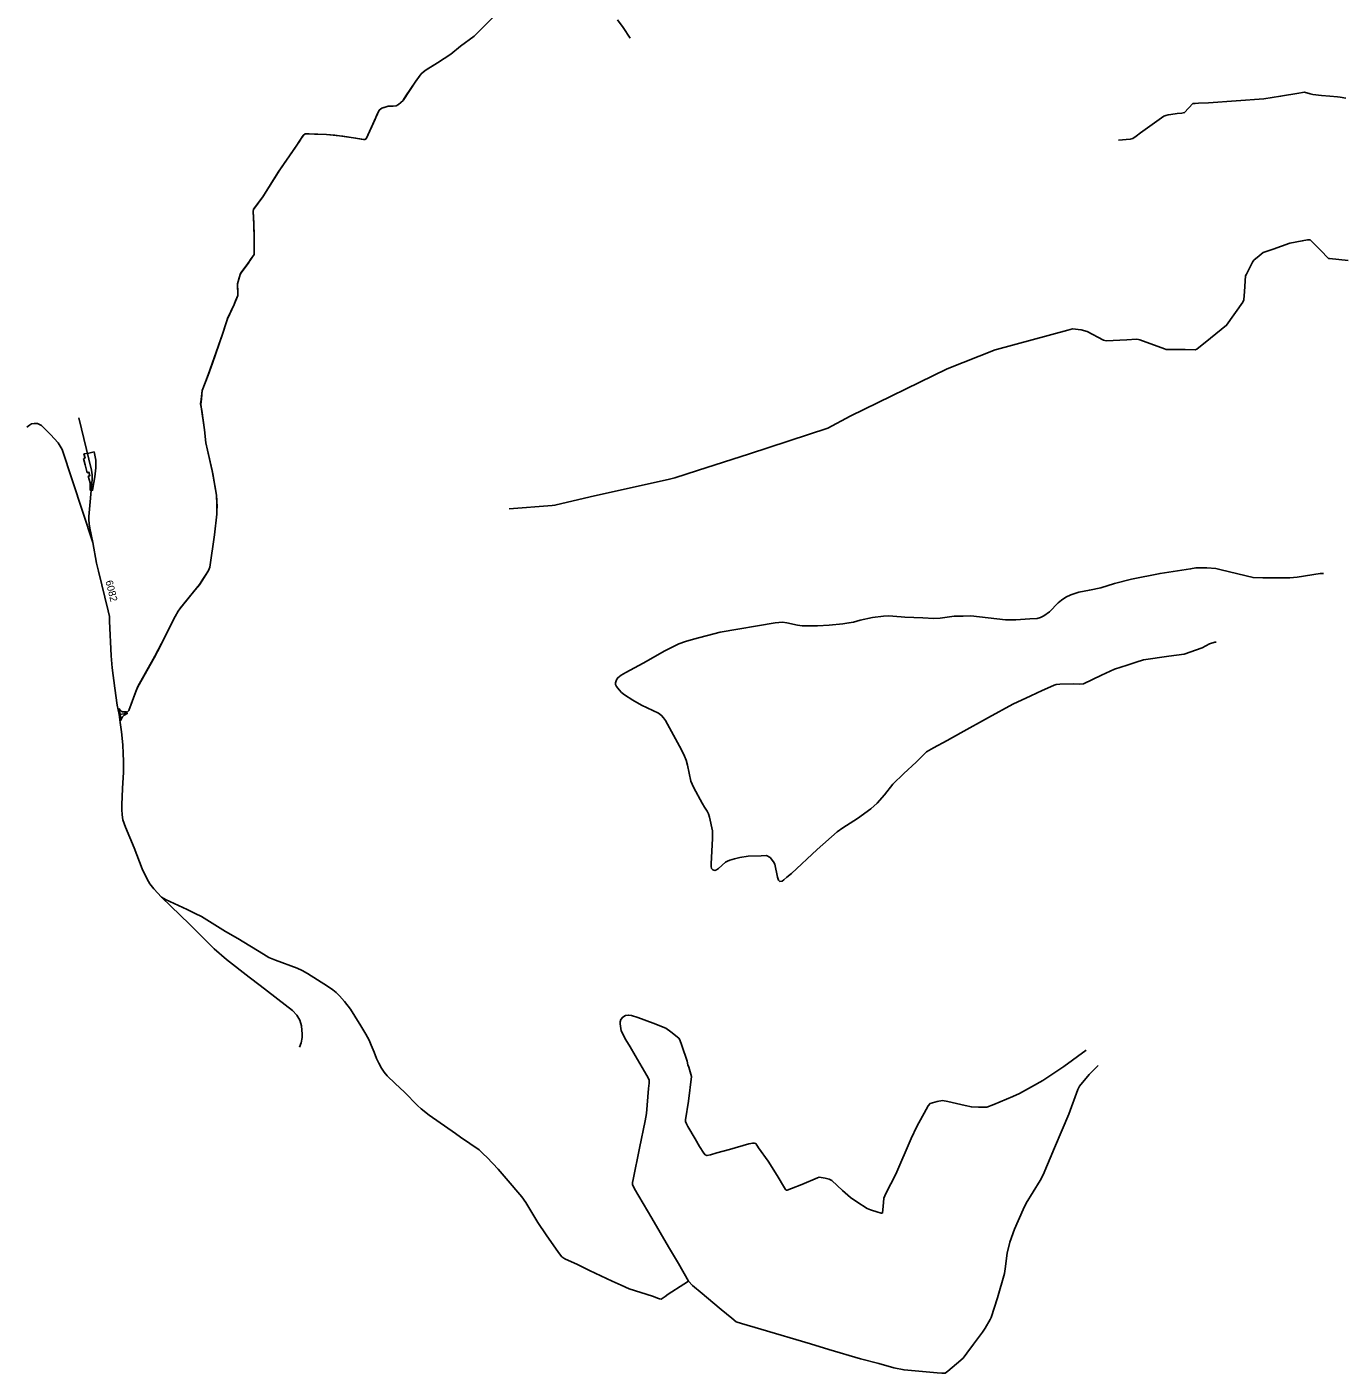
# Model space of a CAD drawing. Extents: x -444937 to -440733, y -1145714 to -1129798.
# Drawn here: x -444937 to -443130, y -1134559 to -1132712 of the extents above; entities that cross this region are included whole.
import ezdxf

# ---------------------------------------------------------------- set-up
doc = ezdxf.new("R2010")
doc.units = 0
for name, color, linetype in [('Vrstva 12', 7, 'Continuous'), ('Vrstva 29', 7, 'Continuous'), ('Vrstva 75', 7, 'Continuous'), ('Vrstva 8', 7, 'Continuous')]:
    doc.layers.add(name, color=color, linetype=linetype)

msp = doc.modelspace()

# ---------------------------------------------------------------- linework, layer by layer
at = {"layer": 'Vrstva 12'}
for points in [[(-444810.7, -1133655.8), (-444804, -1133654.8), (-444800.5, -1133653.5), (-444797.4, -1133650.5), (-444788, -1133624.4), (-444785.2, -1133617.7), (-444762.9, -1133578.2), (-444754.2, -1133561.6), (-444744.3, -1133542.3), (-444733.8, -1133521.3), (-444729.9, -1133513.9), (-444725.7, -1133508.6), (-444706.5, -1133485), (-444700.6, -1133477.9), (-444694.1, -1133467.9), (-444689.6, -1133460.8), (-444688.1, -1133458.5), (-444686.5, -1133453.9), (-444679.9, -1133409.3), (-444676.7, -1133381.1), (-444676.5, -1133375.2), (-444676.2, -1133370.9), (-444677.2, -1133354.9), (-444683.2, -1133321.2), (-444689.7, -1133293.2), (-444691.9, -1133283), (-444693.6, -1133265.4), (-444697.8, -1133236.9), (-444698.8, -1133230.7), (-444697.9, -1133223), (-444697.5, -1133216.2), (-444696.9, -1133211.3), (-444693.8, -1133203.1), (-444688.5, -1133189.8), (-444682.9, -1133174.4), (-444668.8, -1133134.2), (-444664.8, -1133121.3), (-444662.2, -1133112.9), (-444652.8, -1133093.2), (-444648, -1133081.2), (-444648, -1133075.9), (-444648.2, -1133065.2), (-444644.5, -1133052.1), (-444643.3, -1133049.9), (-444633.9, -1133036.9), (-444630.5, -1133031.8), (-444625.5, -1133024.8), (-444625.5, -1132998.6), (-444626, -1132982.6), (-444626.4, -1132973.1), (-444626.8, -1132966.9), (-444626.8, -1132965.1), (-444626.4, -1132963), (-444613.4, -1132945.4), (-444590.2, -1132908.7), (-444567.2, -1132874.9), (-444563.8, -1132870), (-444559.6, -1132863.3), (-444557.8, -1132861), (-444556, -1132859.6), (-444550.6, -1132859.3), (-444542.8, -1132859.6), (-444526.3, -1132859.9), (-444515, -1132861.1), (-444486, -1132865.2), (-444478.6, -1132866.3), (-444475.4, -1132867), (-444473.5, -1132866.9), (-444472, -1132866.1), (-444454, -1132826.8), (-444450.4, -1132824.1), (-444445.7, -1132822.4), (-444441.8, -1132821.1), (-444435, -1132821.1), (-444430.8, -1132820.8), (-444427.7, -1132819.1), (-444421.2, -1132813.3), (-444403.6, -1132786.9), (-444396.3, -1132776.9), (-444390.9, -1132772.4), (-444374, -1132761.8), (-444355.9, -1132749.9), (-444342.4, -1132738.9), (-444323.9, -1132725.4), (-444287.2, -1132688.4)], [(-444127.1, -1132702.6), (-444119.5, -1132713.5), (-444109.5, -1132728.1)], [(-443439.9, -1132867.8), (-443423.7, -1132866.7), (-443420.1, -1132865.6), (-443415.5, -1132862.2), (-443409.8, -1132858), (-443380.8, -1132837.3), (-443377.7, -1132835.1), (-443374.7, -1132833.9), (-443371.9, -1132833.2), (-443368.2, -1132832.8), (-443359.4, -1132831.3), (-443353.1, -1132830.6), (-443349.3, -1132830.1), (-443338, -1132817.7), (-443334.6, -1132817.5), (-443330, -1132817.3), (-443316.2, -1132816.5), (-443240.3, -1132811), (-443217.5, -1132807.6), (-443192.3, -1132803.2), (-443187.4, -1132802.3), (-443184.6, -1132802.1), (-443177, -1132804.2), (-443173.1, -1132805.2), (-443161.5, -1132806.4), (-443150.1, -1132807.4), (-443139.3, -1132808.4), (-443135.8, -1132808.8), (-443127.9, -1132810.4)], [(-443125, -1133032.9), (-443150.3, -1133030.4), (-443151.9, -1133030.2), (-443153.4, -1133028.6), (-443161.1, -1133020.7), (-443171.9, -1133009.7), (-443177.1, -1133004.4), (-443180.5, -1133004.5), (-443187.7, -1133006.1), (-443204.6, -1133009.4), (-443227.8, -1133017.3), (-443241.4, -1133021.8), (-443246.8, -1133026.4), (-443254.2, -1133032.7), (-443255.9, -1133035.1), (-443264.4, -1133051.8), (-443265.5, -1133053.8), (-443267.2, -1133075.6), (-443268, -1133086.8), (-443269.3, -1133090.1), (-443291.6, -1133121.7), (-443313.7, -1133139.6), (-443332.4, -1133154.8), (-443334.7, -1133155.7), (-443348.2, -1133155.3), (-443372.1, -1133154.9), (-443374.3, -1133154.9), (-443376.7, -1133154.3), (-443410.4, -1133141.9), (-443412.6, -1133141.4), (-443415.2, -1133141.1), (-443428.6, -1133141.8), (-443456.6, -1133143.3), (-443460.3, -1133142.2), (-443482.8, -1133130.4), (-443491, -1133127.9), (-443502.9, -1133126.9), (-443509.5, -1133128.6), (-443607.2, -1133155.1), (-443609.1, -1133155.6), (-443674.9, -1133181.8), (-443807.9, -1133246.7), (-443838.6, -1133262.8), (-443946.2, -1133298.1), (-444017.4, -1133320.9), (-444048.5, -1133331.1), (-444055.6, -1133332.9), (-444164.4, -1133357.4), (-444213, -1133368.8), (-444216.8, -1133369.2), (-444275.6, -1133373.9)], [(-444846.6, -1133419.8), (-444888.9, -1133292.1), (-444894.2, -1133283), (-444904.8, -1133271.9), (-444917.3, -1133259.2), (-444922.8, -1133256.5), (-444926.9, -1133256.5), (-444931, -1133257.2), (-444933.6, -1133258.7), (-444937.2, -1133261.6)], [(-444029.7, -1134433.4), (-444036.1, -1134437.5), (-444057.5, -1134451.4), (-444061.9, -1134454.6), (-444067.2, -1134458.1), (-444069.4, -1134457.7), (-444070.7, -1134457.1), (-444079.3, -1134454.1), (-444111.2, -1134443.9), (-444122.2, -1134438.9), (-444134.5, -1134433.4), (-444165.4, -1134418.5), (-444181.8, -1134410.6), (-444199.3, -1134402.5), (-444203.3, -1134400.1), (-444208.1, -1134393.8), (-444224.9, -1134369.7), (-444236.5, -1134352.7), (-444252.8, -1134325.6), (-444258.3, -1134317.7), (-444279.7, -1134292.7), (-444290.6, -1134279.9), (-444306, -1134263.8), (-444311.2, -1134258.5), (-444316.9, -1134253.2), (-444342.3, -1134235.7), (-444349.4, -1134230.9), (-444385.3, -1134205.4), (-444396.4, -1134196.8), (-444401.3, -1134192.1), (-444419.3, -1134173.8), (-444432.2, -1134162.1), (-444443.1, -1134151.6), (-444447.4, -1134146.5), (-444450.9, -1134140.9), (-444454.5, -1134134.2), (-444457.5, -1134127.9), (-444461.1, -1134119.1), (-444464.8, -1134109.5), (-444467.8, -1134102.9), (-444472.3, -1134094.3), (-444479, -1134082.8), (-444487.5, -1134069.6), (-444493.5, -1134060.2), (-444501.4, -1134049.5), (-444508.3, -1134041.9), (-444512.9, -1134037.4), (-444517.8, -1134033.5), (-444524.9, -1134028.5), (-444552.5, -1134011.3), (-444559.6, -1134007.3), (-444566.4, -1134004), (-444596.2, -1133993.1), (-444605.2, -1133989.1), (-444612.7, -1133984.7), (-444647.7, -1133963.4), (-444664.8, -1133953.5), (-444697.7, -1133932.8), (-444706.4, -1133928.7), (-444717.5, -1133923.6), (-444747.3, -1133909.8), (-444752.5, -1133906.4), (-444763, -1133895.2), (-444768.5, -1133888), (-444772.2, -1133882), (-444779.1, -1133867.6), (-444790.3, -1133838.9), (-444802.2, -1133810.5), (-444805.5, -1133800.4), (-444806.7, -1133793.6), (-444807.1, -1133786.4), (-444807.1, -1133780), (-444806.1, -1133757.2), (-444804.8, -1133734.8), (-444804.8, -1133720), (-444805.1, -1133709.2), (-444805.6, -1133697.4), (-444807.3, -1133679.6), (-444809.1, -1133666.7), (-444810.7, -1133655.8), (-444813.3, -1133643), (-444816.6, -1133619.9), (-444820.5, -1133591.7), (-444821.8, -1133575.2), (-444823.9, -1133527.7), (-444824, -1133521.2), (-444825.6, -1133513.8), (-444839.1, -1133459.1), (-444841.7, -1133448.2), (-444846.6, -1133419.8), (-444851.1, -1133400.2), (-444851.9, -1133394.3), (-444852.4, -1133388.4), (-444852.2, -1133384.1), (-444847.6, -1133333.3), (-444847.7, -1133327.2), (-444848.7, -1133320.5), (-444865.8, -1133249)], [(-443836.6, -1133533.2), (-443852.8, -1133534.1), (-443865.6, -1133534.4), (-443873.8, -1133534), (-443880.1, -1133533.4), (-443894.7, -1133530.3), (-443900.7, -1133529.4), (-443906, -1133529.7), (-443910.9, -1133530.2), (-443986.1, -1133542.8), (-444023, -1133552.5), (-444033.6, -1133555.6), (-444043.1, -1133559.1), (-444062.1, -1133568.4), (-444091.9, -1133585.3), (-444115.8, -1133598.1), (-444122.2, -1133601.8), (-444126.7, -1133605.4), (-444128.5, -1133608.4), (-444129.8, -1133612.3), (-444129.7, -1133614.7), (-444128.6, -1133617.3), (-444125, -1133622.1), (-444121.5, -1133625.8), (-444117.7, -1133628.7), (-444106.1, -1133636.3), (-444094.4, -1133642.9), (-444070.8, -1133654.2), (-444066.7, -1133657.1), (-444063.8, -1133660.4), (-444061.3, -1133664.1), (-444039.2, -1133704.5), (-444035.2, -1133713.2), (-444033, -1133718.7), (-444031.1, -1133725.3), (-444026.3, -1133747.2), (-444024.7, -1133751.6), (-444022.2, -1133756.3), (-444010.9, -1133777.6), (-444007.6, -1133782.8), (-444004.1, -1133788.4), (-444002.5, -1133792.3), (-444000.9, -1133796.8), (-443997, -1133815.4), (-443996.7, -1133820.5), (-443996.9, -1133826.1), (-443998.8, -1133860.7), (-443998.7, -1133864.5), (-443998.1, -1133867.1), (-443996.3, -1133869), (-443993.5, -1133869.7), (-443991.1, -1133869), (-443988.7, -1133867.1), (-443978.8, -1133858.3), (-443976.2, -1133857.1), (-443973, -1133855.6), (-443966.4, -1133854)], [(-444752.5, -1133906.4), (-444714.3, -1133943.6), (-444690.6, -1133967.1), (-444680.3, -1133977.2), (-444663.5, -1133991.8), (-444632.4, -1134016.4), (-444617.4, -1134027.5), (-444572.8, -1134062), (-444567, -1134068.4), (-444562.9, -1134075.2), (-444560.5, -1134083), (-444559.5, -1134094.5), (-444559.8, -1134098.9), (-444561.2, -1134106.4), (-444563.2, -1134112.5)], [(-443484.1, -1134116.4), (-443514.7, -1134139), (-443543.5, -1134158.2), (-443559.3, -1134166.8), (-443575.7, -1134176), (-443584.9, -1134179.9), (-443610.7, -1134190.8), (-443620.5, -1134194.8), (-443625.4, -1134194.8), (-443631.8, -1134194.7), (-443641.6, -1134194.3), (-443650.1, -1134192.4), (-443673.9, -1134186.9), (-443681.3, -1134185.5), (-443688.6, -1134187), (-443698.2, -1134189.6), (-443700.8, -1134193), (-443703.6, -1134197.9), (-443716.7, -1134221.2), (-443724.1, -1134237.5), (-443745.2, -1134286.4), (-443758.8, -1134313), (-443761.6, -1134319.6), (-443762.5, -1134331.1), (-443763.4, -1134339.6), (-443764.2, -1134340.2), (-443765.2, -1134340), (-443767, -1134339.5), (-443769.9, -1134338.8), (-443780.2, -1134335.3), (-443784.7, -1134333.7), (-443798.9, -1134324.4), (-443807.6, -1134318.7), (-443818.6, -1134308.9), (-443833.3, -1134295.2), (-443836.8, -1134293.6), (-443842.3, -1134292.1), (-443850.5, -1134290.6), (-443852.9, -1134291.6), (-443874.3, -1134300.5), (-443888.5, -1134306.4), (-443894.5, -1134308.7), (-443895.8, -1134308.5), (-443896.7, -1134307.7), (-443898.2, -1134305.2), (-443908.3, -1134288.4), (-443920.4, -1134268.7), (-443933.6, -1134250.4), (-443937.5, -1134244.5), (-443939.2, -1134243.8), (-443941.5, -1134243.8), (-443947, -1134245.1), (-443973.5, -1134252.5), (-443990.8, -1134257.4), (-443999.4, -1134260.1), (-444004.4, -1134261.1), (-444006.8, -1134260), (-444008.8, -1134257.8), (-444014.4, -1134248.4), (-444020.6, -1134238.2), (-444030.5, -1134221), (-444032.6, -1134217.5), (-444034, -1134214.4), (-444033.9, -1134212), (-444029.5, -1134186.5), (-444025.4, -1134152.4), (-444029.4, -1134139.8), (-444030.5, -1134136.4), (-444031.7, -1134131.3), (-444038.7, -1134109.9), (-444041.4, -1134102.2), (-444042.9, -1134100.1), (-444054.1, -1134091.3), (-444060.9, -1134086.3), (-444078.2, -1134079.3), (-444099.3, -1134071.7), (-444107.9, -1134068.9), (-444112.2, -1134068.2), (-444116, -1134069), (-444119.9, -1134071.1), (-444122.6, -1134074.3), (-444123.3, -1134077.4), (-444123.6, -1134080.2), (-444122.3, -1134089.9), (-444115.6, -1134102.4), (-444109.9, -1134112), (-444103, -1134123.5), (-444086.9, -1134151.2), (-444083.6, -1134157.3), (-444083.7, -1134161.7), (-444084.5, -1134168.8), (-444087.3, -1134203.1), (-444089, -1134213.2), (-444096.9, -1134250.7), (-444105.5, -1134293.7), (-444106.7, -1134298), (-444106.6, -1134300.6), (-444103.8, -1134306.6), (-444079.9, -1134346.7), (-444057.3, -1134386.2), (-444043.6, -1134409.3), (-444029.7, -1134433.4), (-444024.2, -1134439.2), (-444010.8, -1134450.3), (-443996.1, -1134462.6), (-443984.9, -1134472), (-443970.2, -1134484.1), (-443964.2, -1134489.1), (-443957.2, -1134491.3)], [(-443957.2, -1134491.3), (-443930.4, -1134499.2), (-443862.4, -1134519.2), (-443837.3, -1134527), (-443793.8, -1134539.9), (-443768.7, -1134546.1), (-443748, -1134552.3), (-443733.9, -1134555.2), (-443688.5, -1134559.2), (-443682.3, -1134559.4), (-443677.6, -1134559.4), (-443673.9, -1134556.8), (-443662.1, -1134546.8), (-443653.1, -1134538.9), (-443648.1, -1134531.9), (-443638.9, -1134519.8), (-443626.6, -1134503.3), (-443622.9, -1134497.7), (-443615.9, -1134486), (-443614.4, -1134483), (-443605.7, -1134456.1), (-443596.4, -1134422.7), (-443595.2, -1134416.4), (-443592.5, -1134394.8), (-443588.9, -1134380), (-443582.3, -1134361.9), (-443570.7, -1134335), (-443566.3, -1134326.5), (-443547.4, -1134295.2), (-443543.4, -1134287.6), (-443527.8, -1134250.5), (-443517.1, -1134225.7), (-443508.2, -1134204.4), (-443495.7, -1134170.2), (-443493.2, -1134165.6), (-443479.9, -1134149.8), (-443467.6, -1134137.6)]]:
    msp.add_lwpolyline(points, dxfattribs=at)
msp.add_lwpolyline([(-444811, -1133647.8), (-444809.5, -1133650.1), (-444808.1, -1133651.4), (-444806, -1133652.2), (-444804.1, -1133652.3), (-444801, -1133652), (-444799.6, -1133654.6), (-444803.9, -1133656.8), (-444806.2, -1133659), (-444807.2, -1133660.7), (-444808.2, -1133663.7), (-444809.5, -1133655.4)], close=True, dxfattribs=at)
at = {"layer": 'Vrstva 29'}
msp.add_lwpolyline([(-444859.5, -1133304.6), (-444857.2, -1133313.2), (-444854.4, -1133324.1), (-444852.2, -1133323.5), (-444850.8, -1133328.2), (-444853, -1133328.8), (-444851.8, -1133333.5), (-444850.7, -1133337.8), (-444850.5, -1133339.9), (-444850.7, -1133348), (-444847.2, -1133348.3), (-444844.1, -1133329.9), (-444842.7, -1133317.6), (-444842.7, -1133311.8), (-444842.7, -1133306.7), (-444845.1, -1133295.5), (-444852.5, -1133297.1), (-444859, -1133298.4), (-444857.5, -1133304.1)], close=True, dxfattribs=at)
at = {"layer": 'Vrstva 75'}
for points in [[(-444810.7, -1133655.8), (-444804, -1133654.8), (-444800.5, -1133653.5), (-444797.4, -1133650.5), (-444788.5, -1133625.9), (-444786, -1133619.8), (-444785, -1133617.6), (-444763.9, -1133579.9), (-444761.6, -1133575.9), (-444752.5, -1133558.3), (-444733.8, -1133521.3), (-444729.9, -1133513.9), (-444726.6, -1133509.7), (-444708.6, -1133487.7), (-444700.6, -1133477.5), (-444694.8, -1133468.9), (-444691.4, -1133463.5), (-444688.3, -1133458.5), (-444686.5, -1133453.9), (-444679.9, -1133409.3), (-444676.7, -1133381.1), (-444676.5, -1133375.2), (-444676.8, -1133367.2), (-444677.2, -1133354.9), (-444682.3, -1133325.5), (-444689.7, -1133293.2), (-444691.9, -1133283), (-444693.6, -1133265.4), (-444697.5, -1133238.8), (-444699.1, -1133229.4), (-444698.1, -1133223.9), (-444697.1, -1133215.4), (-444696.9, -1133211.3), (-444688.7, -1133190.2), (-444682.7, -1133174), (-444668.8, -1133134.2), (-444663.2, -1133115.9), (-444662.2, -1133112.7), (-444652.8, -1133093.2), (-444651.2, -1133088.2), (-444649.3, -1133084.2), (-444648, -1133081.2), (-444648.2, -1133065.2), (-444645.9, -1133056.8), (-444644.5, -1133052.1), (-444643.6, -1133050.1), (-444634.4, -1133037.3), (-444630.5, -1133031.9), (-444627.8, -1133027.9), (-444625.5, -1133024.8), (-444625.5, -1133001.4), (-444626, -1132985.2), (-444626.4, -1132973.1), (-444626.9, -1132965.7), (-444626.4, -1132962.7), (-444613.4, -1132945.4), (-444592.4, -1132911.9), (-444569, -1132877.6), (-444561.9, -1132866.9), (-444557.9, -1132860.8), (-444555.7, -1132859.4), (-444550.1, -1132859.3), (-444526.3, -1132859.9), (-444503.9, -1132862.6), (-444477.9, -1132866.3), (-444475, -1132867), (-444473.5, -1132866.9), (-444472.8, -1132866.6), (-444471.5, -1132865.1), (-444459.6, -1132839), (-444457.5, -1132834.4), (-444456.7, -1132832.4), (-444455.7, -1132830.2), (-444454, -1132826.8), (-444450.4, -1132824.1), (-444441.8, -1132821.1), (-444430.8, -1132820.7), (-444427.6, -1132818.9), (-444421.2, -1132812.9), (-444417.3, -1132807.1), (-444404.6, -1132788.2), (-444396.3, -1132776.9), (-444389.5, -1132771.3), (-444374, -1132761.8), (-444355.9, -1132749.9), (-444342.4, -1132738.9), (-444323.9, -1132725.4), (-444286.2, -1132687.7)], [(-444846.6, -1133419.8), (-444888.9, -1133292.1), (-444894.2, -1133283), (-444904.8, -1133271.9), (-444917.3, -1133259.2), (-444922.8, -1133256.5), (-444926.9, -1133256.5), (-444931, -1133257.2), (-444933.6, -1133258.7), (-444937.2, -1133261.6)], [(-444810.7, -1133655.8), (-444813.3, -1133643), (-444816.6, -1133619.9), (-444820.5, -1133591.7), (-444821.8, -1133575.2), (-444823.9, -1133527.7), (-444824, -1133521.2), (-444825.6, -1133513.8), (-444839.1, -1133459.1), (-444841.7, -1133448.2), (-444846.6, -1133419.8)]]:
    msp.add_lwpolyline(points, dxfattribs=at)
at = {"layer": 'Vrstva 8'}
for points in [[(-443158.7, -1133462.4), (-443163, -1133462.4), (-443194.6, -1133467.5), (-443204.6, -1133468.4), (-443226.3, -1133468.5), (-443241.7, -1133468.4), (-443255.2, -1133468), (-443299.1, -1133457.3), (-443306.5, -1133455.6), (-443318.9, -1133454.6), (-443333.9, -1133454.8), (-443340.9, -1133456.1), (-443382.8, -1133462.2), (-443421.9, -1133470.3), (-443445.5, -1133476.3), (-443463.9, -1133482.2), (-443479.7, -1133485.2), (-443494.3, -1133488), (-443505.2, -1133491.7), (-443512, -1133495.1), (-443517.9, -1133498.8), (-443522.8, -1133502.5), (-443534.7, -1133515.1), (-443542.3, -1133520.7), (-443546.8, -1133522.9), (-443551.5, -1133524), (-443561.5, -1133524.5), (-443580.6, -1133525.8), (-443589, -1133526.2), (-443594.7, -1133525.8), (-443642.6, -1133520.7), (-443653, -1133520.9), (-443665.4, -1133520.9), (-443684.5, -1133523.7), (-443693.2, -1133524.3), (-443708.2, -1133523.3), (-443732.9, -1133522.3), (-443738.1, -1133521.9), (-443755.2, -1133520.4), (-443762.1, -1133520.8), (-443777.2, -1133522.6), (-443794.2, -1133526.3), (-443803.5, -1133529), (-443809.7, -1133530.3), (-443818, -1133531.6), (-443836.6, -1133533.2)], [(-443966.8, -1133853.9), (-443959.4, -1133852.2), (-443947.9, -1133850.4), (-443930.2, -1133849.6), (-443922.8, -1133849.4), (-443917.7, -1133851.9), (-443913.3, -1133858), (-443911.1, -1133861.2), (-443907.7, -1133879.2), (-443906.3, -1133883.2), (-443904.2, -1133884.8), (-443901.1, -1133884.5), (-443898.8, -1133882.7), (-443894.8, -1133879), (-443888.3, -1133874.2), (-443853.4, -1133841.2), (-443825.7, -1133816.8), (-443817.9, -1133811.2), (-443797.8, -1133798.7), (-443779.8, -1133785.1), (-443771.1, -1133777.7), (-443760.9, -1133765.9), (-443749.4, -1133751.6), (-443734.5, -1133736.6), (-443717.3, -1133721.1), (-443703, -1133707.1), (-443693.6, -1133701.4), (-443674.7, -1133691.6), (-443656, -1133681), (-443618.2, -1133660.1), (-443585, -1133641.8), (-443560.2, -1133630.3), (-443544.7, -1133622.8), (-443533.2, -1133618), (-443528, -1133615.8), (-443525.2, -1133614.9), (-443520.3, -1133614.2), (-443501.1, -1133613.9), (-443493.9, -1133614.2), (-443488, -1133613.6), (-443463, -1133601.9), (-443445.3, -1133593.6), (-443427.9, -1133588.4), (-443415.5, -1133584.1), (-443405.5, -1133580.8), (-443370.9, -1133575.9), (-443349.8, -1133573.1), (-443325.2, -1133564.6), (-443315, -1133559), (-443307.7, -1133556.4), (-443305.9, -1133556.4)]]:
    msp.add_lwpolyline(points, dxfattribs=at)

# ---------------------------------------------------------------- texts
at = {"layer": 'Vrstva 75'}
msp.add_text('6082', height=10, rotation=283.7919, dxfattribs=at).set_placement((-444829.5, -1133473))

doc.saveas('drawing.dxf')
